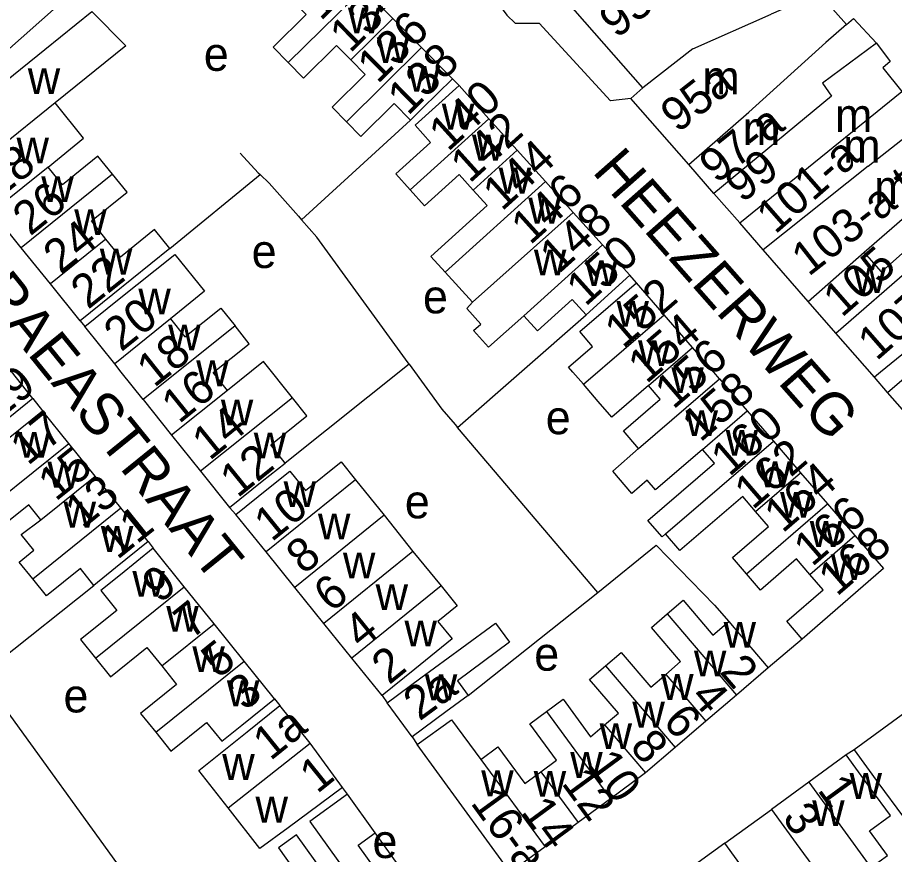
# Model space of a CAD drawing. Extents: x 161141 to 163125, y 381621 to 383200.
# Drawn here: x 162220.2 to 162324.6, y 381942.6 to 382042.2 of the extents above; entities that cross this region are included whole.
import ezdxf

# ---------------------------------------------------------------- set-up
doc = ezdxf.new("R2010")
doc.units = 0
for name, color, linetype in [('BLT_Basislijn', 7, 'Continuous'), ('BLT_Bebouwing', 7, 'Continuous'), ('BLT_Centroide', 7, 'Continuous'), ('BLT_Huisnummer', 7, 'Continuous'), ('BLT_Huisnummer_ tussenligend', 7, 'Continuous'), ('BLT_Huisnummer_reeks', 7, 'Continuous'), ('BLT_Onderverdeling_panden', 7, 'Continuous'), ('BLT_Straatnaam', 7, 'Continuous')]:
    doc.layers.add(name, color=color, linetype=linetype)

msp = doc.modelspace()

# ---------------------------------------------------------------- linework, layer by layer
at = {"layer": 'BLT_Basislijn'}
for p, q in [((162225.91, 382044.48), (162215.44, 382035.2)), ((162272.78, 382034.12), (162271.99, 382034.94)), ((162254.03, 382018.13), (162266.99, 382030)), ((162238.34, 382014.73), (162249.09, 382023.52)), ((162293.91, 382010.63), (162293.12, 382011.53)), ((162272.61, 381993.42), (162287.9, 382006.82)), ((162227.66, 382006.11), (162228.21, 382005.43)), ((162266.85, 382000.96), (162252.08, 381989.18)), ((162323.82, 381997.58), (162322.24, 381999.4)), ((162222.02, 381996.85), (162223.17, 381995.39)), ((162289.3, 381973.75), (162272.61, 381993.42)), ((162245.45, 381983.87), (162246.2, 381983.04)), ((162235.75, 381979.83), (162236.36, 381979.02)), ((162215.8, 381963.9), (162229.3, 381974.61)), ((162273.88, 381961.5), (162289.3, 381973.75)), ((162313.65, 381968.21), (162309.61, 381964.78)), ((162217.71, 381961.28), (162233.44, 381939.6)), ((162250.8, 381961.09), (162251.43, 381960.31)), ((162263.62, 381961.49), (162264.22, 381960.64)), ((162267.19, 381956.59), (162267.8, 381955.67)), ((162319.84, 381955.03), (162318.89, 381954.42)), ((162259.49, 381949.73), (162258.91, 381950.54)), ((162304.44, 381943.91), (162309.98, 381947.93)), ((162265.74, 381941.06), (162262.79, 381945.15))]:
    msp.add_line(p, q, dxfattribs=at)
for points in [[(162278.37, 382051.18), (162277.29, 382049.53), (162276.62, 382047.85), (162276.54, 382046.51), (162276.87, 382045.09), (162277.54, 382043.75), (162278.46, 382042.49), (162279.47, 382041.57), (162282.31, 382041.57)], [(162293.24, 382032.6), (162290.81, 382032.3), (162282.31, 382041.57)], [(162246.73, 382026.06), (162248.85, 382023.74), (162249.09, 382023.52)], [(162249.09, 382023.52), (162250.17, 382022.51), (162253.65, 382018.56), (162254.03, 382018.13)], [(162266.85, 382000.96), (162266.42, 382001.55), (162255.83, 382016.09), (162254.03, 382018.13)], [(162266.85, 382000.96), (162270.72, 381995.6), (162272.31, 381993.77), (162272.61, 381993.42)], [(162289.3, 381973.75), (162296.25, 381979.41), (162303.18, 381972.26), (162304.9, 381970.29)]]:
    msp.add_lwpolyline(points, dxfattribs=at)
at = {"layer": 'BLT_Bebouwing'}
for p, q in [((162264.9, 382042.12), (162261.38, 382045.68)), ((162268.32, 382038.65), (162264.9, 382042.12)), ((162271.99, 382034.94), (162268.32, 382038.65)), ((162276.33, 382030.17), (162272.78, 382034.12)), ((162293.24, 382032.6), (162294.65, 382033.84)), ((162300.14, 382024.71), (162293.24, 382032.6)), ((162279.71, 382026.42), (162276.33, 382030.17)), ((162283.07, 382022.69), (162279.71, 382026.42)), ((162303.12, 382021.29), (162300.14, 382024.71)), ((162286.38, 382019.01), (162283.07, 382022.69)), ((162306.2, 382017.76), (162303.12, 382021.29)), ((162220.65, 382014.79), (162217.2, 382019.07)), ((162289.86, 382015.15), (162286.38, 382019.01)), ((162321.04, 382014.27), (162326.41, 382018.96)), ((162309, 382014.55), (162306.2, 382017.76)), ((162224.11, 382010.51), (162220.65, 382014.79)), ((162293.12, 382011.53), (162289.86, 382015.15)), ((162314.35, 382008.43), (162309, 382014.55)), ((162271.13, 382011.9), (162274.39, 382008.34)), ((162297.21, 382006.84), (162293.91, 382010.63)), ((162227.66, 382006.11), (162224.11, 382010.51)), ((162317.66, 382004.64), (162314.35, 382008.43)), ((162300.59, 382002.92), (162297.21, 382006.84)), ((162231.78, 382000.97), (162228.21, 382005.43)), ((162222.02, 381996.85), (162218.71, 382001.03)), ((162303.78, 381999.22), (162307.1, 381995.38)), ((162327.47, 381993.38), (162323.82, 381997.58)), ((162222.02, 381996.85), (162215.35, 381991.45)), ((162235.15, 381996.75), (162238.55, 381992.5)), ((162226.3, 381991.52), (162223.17, 381995.39)), ((162307.1, 381995.38), (162310.21, 381991.78)), ((162238.55, 381992.5), (162241.99, 381988.2)), ((162229.44, 381987.63), (162226.3, 381991.52)), ((162310.21, 381991.78), (162313.45, 381988.02)), ((162232.51, 381983.84), (162229.44, 381987.63)), ((162241.99, 381988.2), (162245.45, 381983.87)), ((162313.45, 381988.02), (162316.66, 381984.3)), ((162260.44, 381987.19), (162263.85, 381982.98)), ((162235.75, 381979.83), (162232.51, 381983.84)), ((162316.66, 381984.3), (162319.92, 381980.53)), ((162249.8, 381978.59), (162246.2, 381983.04)), ((162263.85, 381982.98), (162267.29, 381978.64)), ((162240.05, 381974.44), (162236.36, 381979.02)), ((162253.23, 381974.34), (162249.8, 381978.59)), ((162267.29, 381978.64), (162270.65, 381974.56)), ((162243.6, 381970.02), (162240.05, 381974.44)), ((162256.68, 381970.07), (162253.23, 381974.34)), ((162247.18, 381965.58), (162243.6, 381970.02)), ((162260.01, 381965.96), (162256.68, 381970.07)), ((162263.62, 381961.49), (162260.01, 381965.96)), ((162250.8, 381961.09), (162247.18, 381965.58)), ((162309.61, 381964.78), (162305.83, 381961.55)), ((162305.83, 381961.55), (162302.17, 381958.42)), ((162267.19, 381956.59), (162264.22, 381960.64)), ((162255.06, 381955.8), (162251.43, 381960.31)), ((162326.9, 381960.17), (162319.84, 381955.03)), ((162302.17, 381958.42), (162298.52, 381955.3)), ((162258.91, 381950.54), (162255.06, 381955.8)), ((162298.52, 381955.3), (162294.99, 381952.28)), ((162318.89, 381954.42), (162314.43, 381951.18)), ((162314.43, 381951.18), (162309.98, 381947.93)), ((162290.83, 381949.2), (162286.96, 381946.36)), ((162286.96, 381946.36), (162283.03, 381943.47)), ((162304.44, 381943.91), (162298.43, 381939.58))]:
    msp.add_line(p, q, dxfattribs=at)
for points in [[(162294.65, 382033.84), (162283.16, 382046.98), (162292.86, 382058.68)], [(162318.92, 382041.38), (162315.62, 382045.14), (162309.95, 382042.63)], [(162252.81, 382044.4), (162254.59, 382042.6), (162250.63, 382038.69), (162252.44, 382036.86)], [(162210.2, 382027.75), (162214.09, 382030.89), (162229.04, 382042.96), (162233.09, 382038.84), (162224.67, 382032.05)], [(162318.92, 382041.38), (162319.76, 382042.11), (162322.49, 382039.16)], [(162252.44, 382036.86), (162254.26, 382035.02), (162258.19, 382038.91), (162259.89, 382037.18)], [(162322.49, 382039.16), (162324.11, 382037.01), (162323.23, 382036.24), (162325.49, 382033.41)], [(162259.89, 382037.18), (162261.6, 382035.46), (162257.65, 382031.56), (162259.37, 382029.82)], [(162266.99, 382030), (162268.43, 382031.43), (162271.99, 382034.94)], [(162266.95, 382021.71), (162265.24, 382023.61), (162269.39, 382027.35), (162267.55, 382029.4), (162272.78, 382034.12)], [(162223.84, 382024.42), (162228.04, 382027.87), (162224.67, 382032.05)], [(162259.37, 382029.82), (162261.09, 382028.07), (162265.04, 382031.97), (162266.99, 382030)], [(162231.51, 382023.56), (162229.78, 382025.7), (162225.56, 382022.29), (162223.84, 382024.42)], [(162230.73, 382015.85), (162229, 382018), (162233.24, 382021.42), (162231.51, 382023.56)], [(162274.47, 382021.68), (162272.79, 382023.54), (162268.67, 382019.81), (162266.95, 382021.71)], [(162271.13, 382011.9), (162269.43, 382013.78), (162276.14, 382019.83), (162274.47, 382021.68)], [(162238.34, 382014.73), (162236.51, 382016.97), (162232.47, 382013.71), (162230.73, 382015.85)], [(162238.34, 382014.73), (162231.55, 382009.25), (162227.66, 382006.11)], [(162228.21, 382005.43), (162232.12, 382008.56), (162238.93, 382014), (162242.46, 382009.64), (162238.42, 382006.34)], [(162327.19, 382012.97), (162325.91, 382014.43), (162323.07, 382011.95), (162321.04, 382014.27)], [(162287.58, 381998.55), (162286.33, 382000), (162285.82, 382000.6), (162288.69, 382003.07), (162287.18, 382004.83), (162293.91, 382010.63)], [(162293.12, 382011.53), (162287.9, 382006.82)], [(162287.9, 382006.82), (162286.24, 382008.65), (162282.11, 382004.93), (162280.51, 382006.7)], [(162238.42, 382006.34), (162240.14, 382004.2), (162244.41, 382007.62), (162246.11, 382005.5)], [(162280.51, 382006.7), (162276.27, 382002.98), (162274.49, 382004.94), (162275.37, 382005.72), (162273.69, 382007.58), (162274.39, 382008.34)], [(162332.44, 382007.71), (162326.13, 382002.57), (162322.98, 382000), (162322.24, 381999.4)], [(162245.21, 381997.82), (162243.5, 381999.95), (162247.8, 382003.38), (162246.11, 382005.5)], [(162322.24, 381999.4), (162317.66, 382004.64)], [(162323.82, 381997.58), (162326.61, 382000), (162327.65, 382000.9), (162330.62, 382003.47), (162332.45, 382001.36), (162335.45, 382003.97), (162337.26, 382001.89)], [(162303.78, 381999.22), (162303.11, 382000), (162300.59, 382002.92)], [(162252.94, 381996.96), (162249.5, 382001.27), (162245.21, 381997.82)], [(162235.15, 381996.75), (162232.55, 382000), (162231.78, 382000.97)], [(162295.35, 381998.39), (162290.97, 381994.62), (162289.35, 381996.49), (162287.58, 381998.55)], [(162294.16, 381990.91), (162292.35, 381993.01), (162296.73, 381996.79), (162295.35, 381998.39)], [(162252.08, 381989.18), (162250.35, 381991.34), (162254.67, 381994.79), (162252.94, 381996.96)], [(162216.71, 381983.8), (162213.59, 381987.65), (162216.72, 381990.18), (162219.28, 381992.25), (162223.17, 381995.39)], [(162301.78, 381990.79), (162296.17, 381985.98), (162295.17, 381987.14), (162293.34, 381985.56), (162291.08, 381988.19), (162294.16, 381990.91)], [(162297.35, 381980.75), (162296.95, 381980.4), (162295.27, 381982.33), (162303.18, 381989.17), (162301.78, 381990.79)], [(162245.45, 381983.87), (162249.35, 381987), (162252.08, 381989.18)], [(162246.2, 381983.04), (162250.09, 381986.18), (162252.61, 381988.22), (162254.49, 381985.89), (162258.73, 381989.32), (162260.44, 381987.19)], [(162308.1, 381983.42), (162306.56, 381985.2), (162299.08, 381978.75), (162297.35, 381980.75)], [(162222.99, 381982.41), (162221.56, 381984.18), (162217.48, 381980.97), (162215.8, 381983.05), (162216.71, 381983.8)], [(162222.02, 381975.37), (162220.39, 381977.39), (162222.14, 381978.81), (162220.64, 381980.67), (162222.99, 381982.41)], [(162307.02, 381975.99), (162305.34, 381977.94), (162309.63, 381981.63), (162308.1, 381983.42)], [(162319.92, 381980.53), (162323.32, 381976.6), (162313.65, 381968.21)], [(162235.75, 381979.83), (162231.87, 381976.68), (162229.3, 381974.61)], [(162236.36, 381979.02), (162232.46, 381975.88), (162230.12, 381973.99), (162232.02, 381971.63), (162227.71, 381968.15), (162229.49, 381965.93)], [(162314.57, 381975.91), (162312.98, 381977.75), (162308.69, 381974.05), (162307.02, 381975.99)], [(162229.3, 381974.61), (162227.69, 381976.61), (162223.65, 381973.35), (162222.02, 381975.37)], [(162313.65, 381968.21), (162311.81, 381970.34), (162316.15, 381974.07), (162314.57, 381975.91)], [(162270.65, 381974.56), (162272.57, 381972.18), (162270.27, 381970.32), (162271.96, 381968.23), (162267.51, 381964.63), (162263.62, 381961.49)], [(162297.58, 381971.21), (162299.47, 381972.83), (162303.01, 381968.68), (162304.9, 381970.29)], [(162297.39, 381964.01), (162299.16, 381965.53), (162295.68, 381969.6), (162297.58, 381971.21)], [(162264.22, 381960.64), (162268.24, 381963.6), (162273.12, 381967.18), (162277.11, 381970.11), (162278.79, 381967.83), (162272.58, 381963.26), (162273.88, 381961.5)], [(162304.9, 381970.29), (162306.36, 381968.58), (162309.61, 381964.78)], [(162229.49, 381965.93), (162231.27, 381963.72), (162235.61, 381967.22), (162237.38, 381965.02)], [(162290.21, 381965.03), (162292.09, 381966.63), (162295.62, 381962.5), (162297.39, 381964.01)], [(162237.38, 381965.02), (162239.15, 381962.82), (162234.86, 381959.35), (162236.66, 381957.11)], [(162290.11, 381957.99), (162291.76, 381959.4), (162288.33, 381963.42), (162290.21, 381965.03)], [(162273.88, 381961.5), (162271.22, 381959.55), (162267.19, 381956.59)], [(162236.66, 381957.11), (162238.47, 381954.87), (162242.71, 381958.29), (162244.53, 381956.04), (162246.9, 381957.95), (162250.8, 381961.09)], [(162283.2, 381959.58), (162285.17, 381961.04), (162288.45, 381956.58), (162290.11, 381957.99)], [(162245.27, 381948.11), (162241.8, 381952.56), (162247.53, 381957.17), (162251.43, 381960.31)], [(162282.52, 381952.41), (162284.4, 381953.8), (162281.22, 381958.13), (162283.2, 381959.58)], [(162267.8, 381955.67), (162271.89, 381958.61), (162275.36, 381953.89)], [(162283.03, 381943.47), (162279.51, 381940.88), (162278.43, 381941.04), (162267.8, 381955.67)], [(162275.36, 381953.89), (162277.41, 381955.4), (162280.63, 381951.02), (162282.52, 381952.41)], [(162321.83, 381941.02), (162323.79, 381942.45), (162321.65, 381945.4), (162324.14, 381947.21), (162321.83, 381950.38), (162318.89, 381954.42)], [(162319.84, 381955.03), (162322.78, 381950.99), (162325.57, 381947.16)], [(162294.99, 381952.28), (162294.83, 381952.15), (162290.83, 381949.2)], [(162258.91, 381950.54), (162254.88, 381947.57), (162252.41, 381945.75)], [(162259.49, 381949.73), (162254.99, 381946.48), (162261.68, 381937.2)], [(162262.79, 381945.15), (162259.49, 381949.73)], [(162252.41, 381945.75), (162249.04, 381943.27), (162245.27, 381948.11)], [(162309.98, 381947.93), (162312.92, 381943.89), (162315.23, 381940.72)], [(162261.68, 381937.2), (162259.89, 381935.91), (162253.44, 381944.91), (162251.27, 381943.35), (162254.58, 381938.73)], [(162265.74, 381941.06), (162263.69, 381939.58), (162260.75, 381943.68), (162262.79, 381945.15)], [(162312.35, 381932.92), (162307.36, 381939.85), (162304.44, 381943.91)]]:
    msp.add_lwpolyline(points, dxfattribs=at)
at = {"layer": 'BLT_Onderverdeling_panden'}
for p, q in [((162252.44, 382036.86), (162261.38, 382045.68)), ((162259.89, 382037.18), (162264.9, 382042.12)), ((162300.6, 382038.49), (162309.95, 382042.63)), ((162307.3, 382030.97), (162316.47, 382039.24)), ((162259.37, 382029.82), (162268.32, 382038.65)), ((162300.6, 382038.49), (162294.65, 382033.84)), ((162306.2, 382017.76), (162325.49, 382033.41)), ((162224.67, 382032.05), (162213.81, 382023.28)), ((162321.48, 382024.51), (162330.68, 382031.78)), ((162300.14, 382024.71), (162307.3, 382030.97)), ((162266.95, 382021.71), (162276.33, 382030.17)), ((162274.47, 382021.68), (162279.71, 382026.42)), ((162223.84, 382024.42), (162217.2, 382019.07)), ((162321.48, 382024.51), (162309, 382014.55)), ((162231.51, 382023.56), (162220.65, 382014.79)), ((162271.13, 382011.9), (162283.07, 382022.69)), ((162274.39, 382008.34), (162286.38, 382019.01)), ((162230.73, 382015.85), (162224.11, 382010.51)), ((162280.51, 382006.7), (162289.86, 382015.15)), ((162314.35, 382008.43), (162321.04, 382014.27)), ((162317.66, 382004.64), (162327.19, 382012.97)), ((162287.58, 381998.55), (162297.21, 382006.84)), ((162238.42, 382006.34), (162231.78, 382000.97)), ((162246.11, 382005.5), (162235.15, 381996.75)), ((162295.35, 381998.39), (162300.59, 382002.92)), ((162294.16, 381990.91), (162303.78, 381999.22)), ((162245.21, 381997.82), (162238.55, 381992.5)), ((162252.94, 381996.96), (162241.99, 381988.2)), ((162301.78, 381990.79), (162307.1, 381995.38)), ((162216.71, 381983.8), (162226.3, 381991.52)), ((162297.35, 381980.75), (162310.21, 381991.78)), ((162222.99, 381982.41), (162229.44, 381987.63)), ((162308.1, 381983.42), (162313.45, 381988.02)), ((162260.44, 381987.19), (162249.8, 381978.59)), ((162222.02, 381975.37), (162232.51, 381983.84)), ((162307.02, 381975.99), (162316.66, 381984.3)), ((162263.85, 381982.98), (162253.23, 381974.34)), ((162314.57, 381975.91), (162319.92, 381980.53)), ((162267.29, 381978.64), (162256.68, 381970.07)), ((162229.49, 381965.93), (162240.05, 381974.44)), ((162270.65, 381974.56), (162260.01, 381965.96)), ((162297.58, 381971.21), (162305.83, 381961.55)), ((162237.38, 381965.02), (162243.6, 381970.02)), ((162236.66, 381957.11), (162247.18, 381965.58)), ((162290.21, 381965.03), (162298.52, 381955.3)), ((162297.39, 381964.01), (162302.17, 381958.42)), ((162283.2, 381959.58), (162290.83, 381949.2)), ((162290.11, 381957.99), (162294.99, 381952.28)), ((162245.27, 381948.11), (162255.06, 381955.8)), ((162275.36, 381953.89), (162283.03, 381943.47)), ((162282.52, 381952.41), (162286.96, 381946.36)), ((162314.43, 381951.18), (162321.83, 381941.02))]:
    msp.add_line(p, q, dxfattribs=at)
for points in [[(162318.92, 382041.38), (162316.47, 382039.24)], [(162322.49, 382039.16), (162316.08, 382034.43), (162317.13, 382032.88), (162303.12, 382021.29)]]:
    msp.add_lwpolyline(points, dxfattribs=at)

# ---------------------------------------------------------------- texts
at = {"layer": 'BLT_Centroide'}
for s, p in [('w', (162259.55, 382040.34)), ('w', (162262.98, 382036.81)), ('e', (162242.38, 382035.88)), ('w', (162221.42, 382033.12)), ('w', (162266.68, 382033.38)), ('m', (162301.75, 382033.09)), ('w', (162270.73, 382028.88)), ('m', (162317.55, 382028.59)), ('m', (162306.56, 382027.03)), ('w', (162220.08, 382024.86)), ('w', (162274.32, 382025.19)), ('m', (162318.53, 382024.94)), ('w', (162277.5, 382021.27)), ('w', (162223.03, 382020.25)), ('m', (162322.21, 382020.03)), ('w', (162281.03, 382017.69)), ('w', (162226.95, 382016.33)), ('e', (162248.08, 382012.4)), ('w', (162230, 382011.62)), ('w', (162281.69, 382011.53)), ('w', (162287.8, 382010.25)), ('w', (162319.76, 382009.41)), ('w', (162234.59, 382006.88)), ('e', (162268.48, 382007)), ('w', (162291.52, 382005.41)), ('w', (162238.14, 382002.59)), ('w', (162294.09, 382000.72)), ('w', (162241.48, 381998.33)), ('w', (162298.06, 381997.52)), ('w', (162244.41, 381993.66)), ('e', (162283.1, 381992.61)), ('w', (162299.75, 381992.38)), ('w', (162220.25, 381989.81)), ('w', (162304.53, 381990.05)), ('w', (162248.33, 381989.73)), ('w', (162223.77, 381986.25)), ('w', (162308.48, 381986.3)), ('w', (162251.88, 381983.94)), ('e', (162266.32, 381982.59)), ('w', (162311, 381982.67)), ('w', (162225.68, 381981.5)), ('w', (162255.98, 381980.08)), ('w', (162230.12, 381978.59)), ('w', (162314.54, 381979.19)), ('w', (162258.95, 381975.44)), ('w', (162317.04, 381975.25)), ('w', (162233.88, 381973.25)), ('w', (162262.84, 381971.66)), ('w', (162237.91, 381969.09)), ('w', (162266.28, 381967.34)), ('w', (162304.28, 381967.19)), ('w', (162241.02, 381964.28)), ('e', (162281.73, 381964.45)), ('w', (162300.75, 381963.78)), ('w', (162268.7, 381960.93)), ('w', (162296.84, 381960.97)), ('e', (162225.67, 381959.48)), ('w', (162245.13, 381960.22)), ('w', (162293.42, 381957.67)), ('w', (162289.52, 381955.12)), ('w', (162244.58, 381951.44)), ('w', (162286.02, 381951.69)), ('w', (162275.42, 381949.5)), ('w', (162281.67, 381949.44)), ('w', (162319.28, 381949.19)), ('w', (162248.54, 381946.36)), ('w', (162314.83, 381945.95)), ('e', (162262.47, 381942.14))]:
    msp.add_text(s, height=4, dxfattribs=at).set_placement(p)
at = {"layer": 'BLT_Huisnummer'}
for s, rotation, p in [('132', 44.637, (162256.31, 382041.74)), ('136', 44.6434, (162263.09, 382034.24)), ('95a', 38.0242, (162298.8, 382028.4)), ('140', 42.0609, (162271.46, 382026.17)), ('144', 42.0626, (162277.88, 382019.08)), ('99', 38.0242, (162306.48, 382020.05)), ('26', 38.9122, (162221.7, 382016.13)), ('148', 42.0571, (162284.66, 382011.64)), ('150', 42.0571, (162287.83, 382007.72)), ('22', 38.6315, (162228.6, 382007.39)), ('152', 40.7579, (162292.31, 382002.72)), ('20', 38.643, (162232.54, 382002.34)), ('156', 40.7518, (162298.29, 381995.47)), ('19', 38.9677, (162217.98, 381994.25)), ('16', 38.9443, (162239.43, 381993.77)), ('17', 38.9677, (162221.42, 381988.79)), ('160', 40.7494, (162304.96, 381987.47)), ('12', 38.9467, (162246.4, 381984.94)), ('164', 40.757, (162311.31, 381980.74)), ('10', 38.9467, (162250.46, 381979.7)), ('11', 38.8526, (162232.09, 381977.59)), ('168', 40.7538, (162317.77, 381973.21)), ('9', 38.8526, (162237.13, 381972.37)), ('6', 38.9298, (162257.56, 381971.28)), ('2', 38.9371, (162264.45, 381962.7)), ('2', 310.5011, (162303.7, 381964.27)), ('3', 38.8531, (162247.27, 381959.58)), ('2a', 36.3382, (162268.07, 381958.38)), ('6', 310.527, (162296.92, 381958.33)), ('1a', 38.8531, (162250.31, 381953.64)), ('10', 306.3371, (162287.99, 381953.19)), ('1', 38.8531, (162255.88, 381949.72)), ('1', 306.0813, (162315.37, 381950.23)), ('14', 306.3265, (162280.05, 381947.62)), ('3', 305.7788, (162311.17, 381946.92))]:
    msp.add_text(s, height=4, rotation=rotation, dxfattribs=at).set_placement(p)
at = {"layer": 'BLT_Huisnummer_ tussenligend'}
for s, rotation, p in [('134', 44.637, (162259.81, 382037.89)), ('138', 44.6434, (162266.69, 382030.45)), ('142', 42.0609, (162274.04, 382022.4)), ('28', 38.9122, (162217.98, 382020.56)), ('146', 42.0626, (162281.25, 382015.05)), ('24', 38.6315, (162225.33, 382011.58)), ('105', 41.1706, (162318.36, 382006.42)), ('154', 40.7579, (162295.09, 381998.52)), ('18', 38.643, (162236.47, 381998.07)), ('158', 40.7518, (162301.51, 381991.56)), ('14', 38.9443, (162243.07, 381989.38)), ('162', 40.7494, (162307.76, 381983.52)), ('15', 38.8492, (162224.74, 381984.53)), ('13', 38.8492, (162227.93, 381981.24)), ('166', 40.757, (162314.82, 381976.74)), ('8', 38.9298, (162254.27, 381975.81)), ('7', 38.8459, (162240.88, 381968.09)), ('4', 38.9371, (162261.14, 381966.94)), ('5', 38.8459, (162244.15, 381963.44)), ('4', 310.5011, (162300.2, 381961.25)), ('8', 310.527, (162293, 381955.32)), ('12', 306.3371, (162284.89, 381951.04))]:
    msp.add_text(s, height=4, rotation=rotation, dxfattribs=at).set_placement(p)
at = {"layer": 'BLT_Huisnummer_reeks'}
for s, rotation, p in [('93-95', 39.0278, (162291.56, 382039.63)), ('97-a', 38.6306, (162303.45, 382022.35)), ('103-a t/m c', 38.0242, (162314.4, 382011.31)), ('101-a', 41.1724, (162310.42, 382016.33)), ('107-a t/m d', 41.1706, (162322.49, 382001.25)), ('16-a', 306.0048, (162274.06, 381948.7))]:
    msp.add_text(s, height=4, rotation=rotation, dxfattribs=at).set_placement(p)
at = {"layer": 'BLT_Straatnaam'}
for s, rotation, p in [('HEEZERWEG', 311.4062, (162288.52, 382023.84)), ('SPIRAEASTRAAT', 308.9763, (162208.67, 382017.77))]:
    msp.add_text(s, height=5, rotation=rotation, dxfattribs=at).set_placement(p)

doc.saveas('drawing.dxf')
